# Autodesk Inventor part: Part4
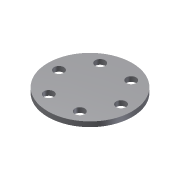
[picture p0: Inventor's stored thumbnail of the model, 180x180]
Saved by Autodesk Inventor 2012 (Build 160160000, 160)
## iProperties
Created: 2008-05
Part Number: Part4
Document SubType Name: Modeling
Designer: CADCIM
Density: 1 g/cm^3
Material: Default
Author: CADCIM
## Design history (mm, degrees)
sketch "Sketch1"
  geometry: C1 r 17 at (0, 0)
  constraints: 1 centre point, 1 other
  dimensions: "d12" = 34 diameter of C1
extrude "Extrusion1" new body sketch "Sketch1" distance "d0" = 2; taper "d1" = 0 deg
sketch "Sketch2"
  geometry: 1 further point
hole "Hole1" sketch "Sketch2" at (5.9, 10.769) diameter "d2" = 4; stored, may be unused: countersink angle "d6" = 90 deg, drill point angle "d8" = 118 deg; dims "d3" = 6, "d4" = 4, "d5" = 2, "d7" = 8
pattern_circular "Circular Pattern1" dims angle "d10" = 360 deg
body "Solid1"
